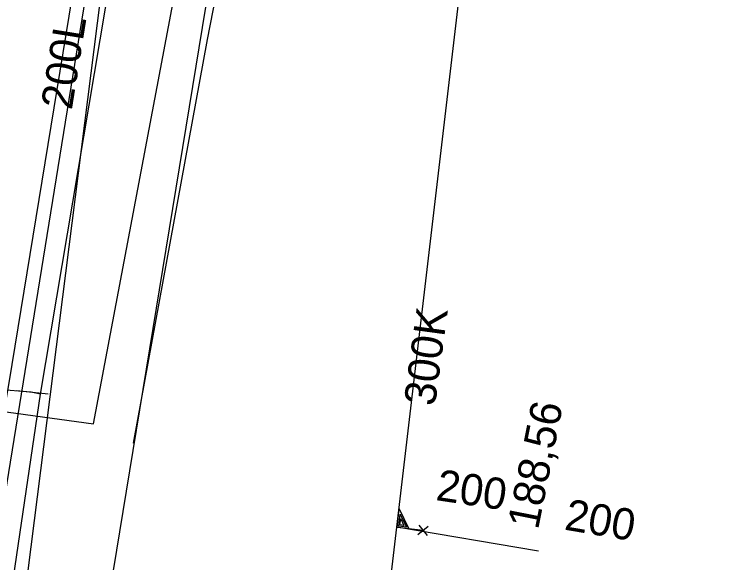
# Model space of a CAD drawing. Extents: x -746464 to -745690, y -1051581 to -1049993.
# Drawn here: x -745944.03 to -745921.55, y -1051098.85 to -1051081.32 of the extents above; entities that cross this region are included whole.
import ezdxf

# ---------------------------------------------------------------- set-up
doc = ezdxf.new("R2010")
doc.units = 0
for name, color, linetype in [('04_CETIN_sdelovaci_podzem', 7, 'Continuous'), ('48_Prazs_plynarenska_STL', 7, 'Continuous'), ('51_PVaK_kanal_jednotna_neoverena poloha_pripojka', 7, 'Continuous'), ('51_PVaK_kanal_jednotna_overena poloha_rad', 7, 'Continuous'), ('51_PVaK_kanal_objekty', 7, 'Continuous'), ('51_PVaK_kanal_popisy', 7, 'Continuous'), ('51_PVaK_vodovod_chranicky_objekty', 7, 'Continuous'), ('51_PVaK_vodovod_overena poloha_rad', 7, 'Continuous'), ('51_PVaK_vodovod_popisy', 7, 'Continuous'), ('51_PVaK_vodovod_zruseno_neoverena poloha', 7, 'Continuous'), ('51_PVaK_vodovod_zruseno_overena poloha', 7, 'Continuous'), ('55_PREdi_NN', 7, 'Continuous')]:
    doc.layers.add(name, color=color, linetype=linetype)

msp = doc.modelspace()

# ---------------------------------------------------------------- linework, layer by layer
at = {"layer": '04_CETIN_sdelovaci_podzem'}
msp.add_lwpolyline([(-745944.47, -1051108.55), (-745944.26, -1051106.63), (-745943.49, -1051101.16), (-745943.58, -1051099.09), (-745941.27, -1051080.85), (-745937.71, -1051064), (-745932.04, -1051060.9), (-745931.63, -1051060.78)], dxfattribs=at)
at = {"layer": '48_Prazs_plynarenska_STL'}
msp.add_lwpolyline([(-745933.53, -1051052.2), (-745934.63, -1051057.86), (-745934.97, -1051061.96), (-745938.95, -1051063.31), (-745941.82, -1051081.15), (-745949.01, -1051125.58), (-745937.91, -1051133.64), (-745924.64, -1051133.98), (-745895.83, -1051134.9), (-745895.22, -1051134.939)], dxfattribs=at)
at = {"layer": '51_PVaK_kanal_jednotna_neoverena poloha_pripojka'}
msp.add_line((-745927.29, -1051098.47), (-745931.806, -1051097.712), dxfattribs=at)
at = {"layer": '51_PVaK_kanal_jednotna_overena poloha_rad'}
msp.add_lwpolyline([(-745934.26, -1051118.57), (-745934.085, -1051117.079), (-745931.806, -1051097.712), (-745928.57, -1051070.202), (-745928.43, -1051069.01)], dxfattribs=at)
at = {"layer": '51_PVaK_kanal_objekty'}
for p, q in [((-745930.804, -1051097.687), (-745931.135, -1051097.948)), ((-745931.103, -1051097.644), (-745930.844, -1051097.97))]:
    msp.add_line(p, q, dxfattribs=at)
for points in [[(-745930.967, -1051097.814), (-745931.804, -1051097.715), (-745931.734, -1051097.118), (-745931.427, -1051097.76)], [(-745931.505, -1051097.706), (-745931.749, -1051097.677), (-745931.704, -1051097.296), (-745931.506, -1051097.71)], [(-745931.588, -1051097.652), (-745931.71, -1051097.637), (-745931.687, -1051097.441), (-745931.589, -1051097.656)]]:
    msp.add_lwpolyline(points, dxfattribs=at)
at = {"layer": '51_PVaK_vodovod_chranicky_objekty'}
msp.add_line((-745942.95, -1051093.46), (-745943.95, -1051093.35), dxfattribs=at)
at = {"layer": '51_PVaK_vodovod_overena poloha_rad'}
msp.add_lwpolyline([(-745890.28, -1051143.51), (-745890.6, -1051140.69), (-745891.93, -1051139.38), (-745893.35, -1051139.24), (-745897.9, -1051139.04), (-745920.34, -1051136.9), (-745943.27, -1051135.95), (-745949.96, -1051125.82), (-745948.83, -1051119.85), (-745944.19, -1051093.1), (-745939.39, -1051063.75), (-745939.34, -1051063.58), (-745938.95, -1051063.31), (-745936.21, -1051061.46), (-745932.65, -1051056.02)], dxfattribs=at)
at = {"layer": '51_PVaK_vodovod_zruseno_neoverena poloha'}
msp.add_lwpolyline([(-745891.087, -1051141.065), (-745891.105, -1051140.7), (-745891.8, -1051140.58), (-745893.65, -1051139.79), (-745920.36, -1051136.38), (-745940.514, -1051133.559), (-745944.966, -1051130.576), (-745947.905, -1051125.405), (-745943.19, -1051093.46), (-745938.18, -1051063.68), (-745937.465, -1051058.828)], dxfattribs=at)
at = {"layer": '51_PVaK_vodovod_zruseno_overena poloha'}
for p, q in [((-745943.49, -1051093.4), (-745945.084, -1051093.264)), ((-745943.19, -1051093.46), (-745943.49, -1051093.4))]:
    msp.add_line(p, q, dxfattribs=at)
at = {"layer": '55_PREdi_NN'}
for points in [[(-745953.293, -1051092.794), (-745941.494, -1051094.409), (-745938.559, -1051078.845), (-745936.337, -1051069.002), (-745934.517, -1051063.745), (-745935.36, -1051054.967), (-745934.146, -1051040.815), (-745949.503, -1051040.147), (-745953.566, -1051039.97), (-745953.607, -1051040.937)], [(-745899.577, -1051066.188), (-745900.355, -1051065.859), (-745901.122, -1051065.59), (-745901.741, -1051065.551), (-745920.055, -1051063.342), (-745933.641, -1051063.88), (-745935.191, -1051069.002), (-745937.596, -1051079.144), (-745942.563, -1051109.421), (-745942.775, -1051115.083), (-745943.148, -1051117.532), (-745941.823, -1051117.532)], [(-745933.852, -1051063.764), (-745937.204, -1051078.752), (-745937.872, -1051082.13), (-745940.23, -1051095.024)]]:
    msp.add_lwpolyline(points, dxfattribs=at)

# ---------------------------------------------------------------- texts
at = {"layer": '51_PVaK_kanal_popisy'}
for s, rotation, p in [('300K', 82.291, (-745930.595, -1051093.865)), ('188,56', 78.7415, (-745927.3, -1051097.814)), ('200', 351.47, (-745930.591, -1051096.84)), ('200', 350.4747, (-745926.488, -1051097.783))]:
    msp.add_text(s, height=1, rotation=rotation, dxfattribs=at).set_placement(p)
at = {"layer": '51_PVaK_vodovod_popisy'}
msp.add_text('200L', height=1, rotation=80.9149, dxfattribs=at).set_placement((-745942.192, -1051084.406))

doc.saveas('drawing.dxf')
